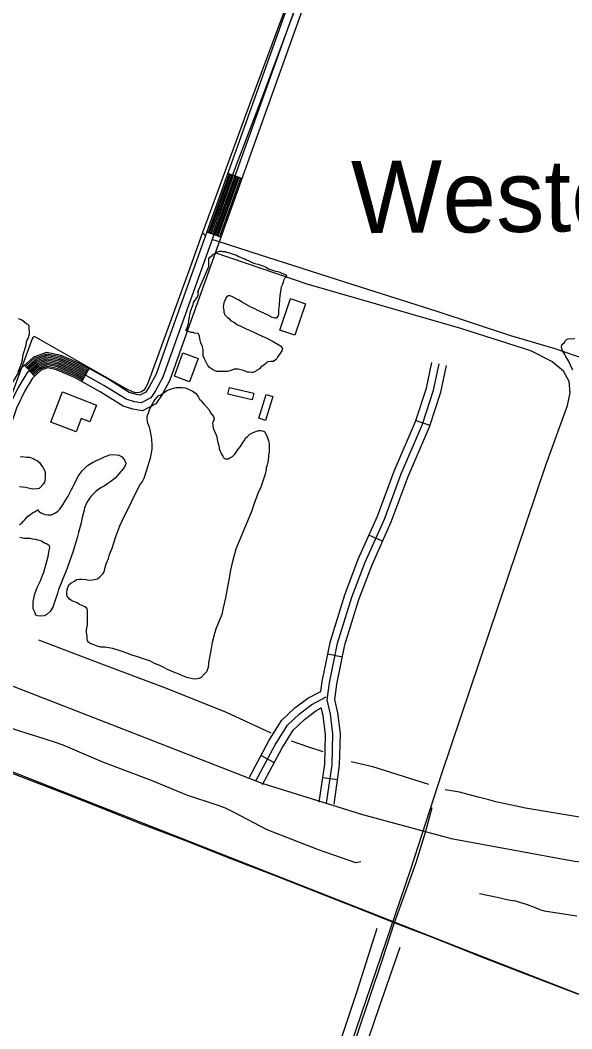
# Model space of a CAD drawing. Extents: x 3281947 to 3319794, y 715894 to 741249.
# Drawn here: x 3298836 to 3299944, y 722569 to 724593 of the extents above; entities that cross this region are included whole.
import ezdxf

# ---------------------------------------------------------------- set-up
doc = ezdxf.new("R2010")
doc.units = 0
for name, color, linetype in [('V-BLDG-OTLN', 7, 'Continuous'), ('V-DTCH-CNTR', 7, 'Continuous'), ('V-RAIL-TRAK', 7, 'Continuous'), ('V-ROAD-CNTR', 7, 'Continuous'), ('V-SITE-VEGE', 7, 'Continuous'), ('V-TOPO-GNAM-IDEN', 7, 'Continuous'), ('V-TOPO-SHOR', 7, 'Continuous')]:
    doc.layers.add(name, color=color, linetype=linetype)

msp = doc.modelspace()

# ---------------------------------------------------------------- linework, layer by layer
at = {"layer": 'V-BLDG-OTLN'}
for points in [[(3299357.2, 723971.1), (3299378.6, 724034.4), (3299409, 724024.1), (3299387.6, 723960.8)], [(3299145.4, 723878.8), (3299162.5, 723925.6), (3299193.1, 723914.3), (3299176, 723867.6)], [(3298920.4, 723847), (3298988.8, 723820.5), (3298975.8, 723787.1), (3298958.2, 723794), (3298947.7, 723766.9), (3298897, 723786.5)], [(3299256.3, 723856.2), (3299304.9, 723844.7), (3299301.7, 723831.1), (3299253, 723842.6)], [(3299315.1, 723794.2), (3299330, 723841.9), (3299343.4, 723837.7), (3299328.4, 723790)]]:
    msp.add_lwpolyline(points, close=True, dxfattribs=at)
at = {"layer": 'V-DTCH-CNTR'}
msp.add_lwpolyline([(3299410.4, 724679), (3299395.7, 724638.7), (3299325.7, 724449.5), (3299265.4, 724291.8), (3299225.3, 724183.4)], dxfattribs=at)
at = {"layer": 'V-RAIL-TRAK'}
for points in [[(3299849.3, 722679.2), (3299761, 722713.5), (3299663.5, 722752.2), (3299603.9, 722774.9), (3299586.9, 722781.6), (3299533.3, 722802.9), (3299451.7, 722834.9), (3299353.4, 722873.6), (3299260.9, 722909.2), (3299166.2, 722946.6), (3299076, 722981.2), (3298988.6, 723015.5), (3298928, 723039.5), (3298835.5, 723075.1), (3298749.5, 723108.4), (3298683, 723135.1), (3298600.1, 723166.2), (3298587.1, 723171.6), (3298582.8, 723173.4), (3298567.7, 723179.4)], [(3299955.5, 722638.3), (3299849.3, 722679.2)]]:
    msp.add_lwpolyline(points, dxfattribs=at)
at = {"layer": 'V-ROAD-CNTR'}
for p, q in [((3299280.7, 724275.3), (3299252.4, 724285.4)), ((3299238.6, 724157.6), (3299210.3, 724167.7)), ((3298864.3, 723878.5), (3298844.4, 723900.9)), ((3298959.4, 723867.8), (3298974, 723894)), ((3299630.3, 723789.9), (3299658.7, 723780.5)), ((3299536.5, 723559.9), (3299563.9, 723547.7)), ((3299453.5, 723321.2), (3299482.9, 723315.2)), ((3299319.6, 723117.7), (3299346, 723103.4)), ((3299443.4, 723073.2), (3299473.1, 723068.9))]:
    msp.add_line(p, q, dxfattribs=at)
for points in [[(3287528.8, 727489.4), (3288159.7, 727246.7), (3289159.6, 726857.6), (3289743.7, 726626.7), (3290210.1, 726446.4), (3290854.7, 726194.3), (3291198.3, 726062.1), (3292329.9, 725616.5), (3292874.1, 725407.4), (3293983.9, 724974.1), (3294772.1, 724664.7), (3295711.6, 724298), (3296794.9, 723876.7), (3297613.5, 723554.1), (3297991.8, 723406.1), (3298815.4, 723086.6), (3299719.3, 722731.4), (3300678.1, 722358.1)], [(3299923.8, 726089.6), (3299901, 726032), (3299863.6, 725936.1), (3299761.7, 725663.6), (3299511.6, 724964.9), (3299148.2, 723949.6), (3299122.2, 723876.9), (3299107.7, 723849.6), (3299098, 723835), (3299078.6, 723825), (3299065.5, 723827.2), (3299048.5, 723832.4), (3299003.8, 723860.3), (3298951.5, 723889.4), (3298913.2, 723905.8), (3298889.6, 723910.7), (3298870.1, 723903.7), (3298848.8, 723884.7), (3298831.4, 723856.2), (3298814, 723820.3), (3298730.5, 723575.4), (3298677.2, 723417.2), (3298650.5, 723323)], [(3299937.8, 726084), (3299915, 726026.5), (3299877.6, 725930.8), (3299775.8, 725658.5), (3299525.7, 724959.8), (3299162.3, 723944.6), (3299136, 723870.8), (3299120.6, 723841.9), (3299108.3, 723823.5), (3299081.1, 723809.3), (3299062, 723812.6), (3299042.2, 723818.6), (3298996.1, 723847.4), (3298944.8, 723875.9), (3298908.7, 723891.5), (3298890.7, 723895.2), (3298877.9, 723890.6), (3298860.4, 723875), (3298844.6, 723849), (3298827.9, 723814.6), (3298744.7, 723570.6), (3298691.5, 723412.7), (3298665, 723318.9)], [(3299763.5, 725711.2), (3299747.6, 725668.8), (3299497.4, 724969.9), (3299134.1, 723954.7), (3299108.5, 723882.9), (3299094.8, 723857.3), (3299087.7, 723846.6), (3299076.2, 723840.6), (3299068.9, 723841.8), (3299054.7, 723846.1), (3299011.4, 723873.2), (3298958.1, 723902.8), (3298917.7, 723920.2), (3298888.5, 723926.2), (3298862.3, 723916.8), (3298837.1, 723894.4), (3298818.3, 723863.4), (3298800.1, 723826), (3298716.3, 723580.2), (3298662.9, 723421.6), (3298636.1, 723327)], [(3293604.8, 725293.3), (3294762.1, 724839.9), (3295753.8, 724453.1), (3296714, 724076.6), (3298094.6, 723538.7), (3299007, 723184.6), (3299321, 723061.9), (3299523.3, 722999.2), (3299701.5, 722950.5), (3299949, 722905.2), (3300134.1, 722886.4), (3300314.5, 722877.1), (3300486.9, 722878.9), (3300681.3, 722895.7), (3300871.4, 722922.7), (3301027.9, 722958.5), (3301177.9, 722998.7), (3301318.6, 723046.1), (3301415.1, 723084.5), (3301509.5, 723122.5), (3301655.6, 723193.6), (3302010.6, 723367.2), (3302498.5, 723608.3), (3302680.4, 723698.6)], [(3299255.3, 724284.4), (3299213.1, 724166.7)], [(3299258.1, 724283.4), (3299216, 724165.7)], [(3299260.9, 724282.4), (3299218.8, 724164.7)], [(3299263.7, 724281.4), (3299221.6, 724163.7)], [(3299266.6, 724280.4), (3299224.4, 724162.7)], [(3299269.4, 724279.3), (3299227.3, 724161.7)], [(3299272.2, 724278.3), (3299230.1, 724160.6)], [(3299275, 724277.3), (3299232.9, 724159.6)], [(3299277.9, 724276.3), (3299235.7, 724158.6)], [(3299081.9, 721282.4), (3299325.2, 722021.3), (3299521.4, 722598.8), (3299619.3, 722887), (3299682.7, 723081.2), (3299891.5, 723700.1), (3299934.8, 723819.8), (3299940.3, 723845.4), (3299938.5, 723867.8), (3299926.8, 723889.1), (3299903.5, 723908.1), (3299861.3, 723929.8), (3299720.6, 723974.7), (3299412.1, 724063.4), (3299227.2, 724126.2)], [(3298972.5, 723891.4), (3298956.8, 723900.1), (3298916.8, 723917.4), (3298888.8, 723923.1), (3298863.8, 723914.2), (3298846.4, 723898.6)], [(3298971.1, 723888.8), (3298955.5, 723897.4), (3298915.9, 723914.5), (3298889, 723920), (3298865.4, 723911.6), (3298848.3, 723896.4)], [(3298969.6, 723886.1), (3298954.1, 723894.7), (3298915, 723911.6), (3298889.2, 723916.9), (3298867, 723909), (3298850.3, 723894.1)], [(3298968.2, 723883.5), (3298952.8, 723892), (3298914.1, 723908.7), (3298889.4, 723913.8), (3298868.5, 723906.3), (3298852.3, 723891.9)], [(3298966.7, 723880.9), (3298951.5, 723889.4), (3298913.2, 723905.8), (3298889.6, 723910.7), (3298870.1, 723903.7), (3298854.3, 723889.7)], [(3298965.2, 723878.3), (3298950.2, 723886.7), (3298912.3, 723903), (3298889.9, 723907.6), (3298871.6, 723901.1), (3298856.3, 723887.4)], [(3299439.4, 723246.1), (3299442.2, 723265.8), (3299458.8, 723346.8), (3299487.5, 723440.1), (3299514.8, 723511.3), (3299553.3, 723597.5), (3299586.8, 723688.2), (3299629.5, 723787.5), (3299651.6, 723854.7), (3299662.6, 723906.5)], [(3298963.8, 723875.7), (3298948.8, 723884), (3298911.4, 723900.1), (3298890.1, 723904.5), (3298873.2, 723898.4), (3298858.3, 723885.2)], [(3298962.3, 723873), (3298947.5, 723881.3), (3298910.5, 723897.2), (3298890.3, 723901.4), (3298874.8, 723895.8), (3298860.3, 723883)], [(3298960.9, 723870.4), (3298946.2, 723878.6), (3298909.6, 723894.3), (3298890.5, 723898.3), (3298876.3, 723893.2), (3298862.3, 723880.7)], [(3299451.1, 723021.6), (3299462.3, 723098.8), (3299463.9, 723160.6), (3299458.9, 723200.4), (3299452.1, 723228.8), (3299457, 723263.2), (3299473.3, 723343.1), (3299501.7, 723435.2), (3299528.7, 723505.6), (3299567.2, 723591.8), (3299600.7, 723682.6), (3299643.5, 723782.2), (3299666.1, 723850.8), (3299677.3, 723903.4)], [(3299466, 723019.4), (3299477.3, 723097.6), (3299478.9, 723161.3), (3299473.6, 723203.1), (3299467.3, 723229.5), (3299471.8, 723260.7), (3299487.9, 723339.3), (3299515.9, 723430.3), (3299542.5, 723499.8), (3299581.1, 723586.2), (3299614.7, 723677.1), (3299657.5, 723776.9), (3299680.6, 723846.9), (3299692, 723900.3)], [(3299295.9, 723073.6), (3299335.2, 723146.6), (3299360.7, 723187.5), (3299387.2, 723212.8), (3299413.6, 723232.5), (3299439.4, 723246.1)], [(3299309.1, 723066.5), (3299348.1, 723139), (3299372.4, 723178), (3299396.9, 723201.3), (3299421.7, 723219.8), (3299450.3, 723234.9)], [(3299322.3, 723059.4), (3299361.1, 723131.5), (3299384.1, 723168.4), (3299406.6, 723189.8), (3299429.7, 723207.1), (3299440.5, 723212.8)], [(3299436.3, 723023.7), (3299447.4, 723100.1), (3299448.9, 723159.8), (3299444.1, 723197.7), (3299440.5, 723212.8)], [(3299662.3, 723012.2), (3299655.1, 722985), (3299649, 722962.8)], [(3299649, 722962.8), (3299630.4, 722902), (3299608, 722840.6), (3299594.3, 722801.8), (3299586.9, 722781.6), (3299562.7, 722707.1), (3299512.6, 722558.3), (3299465.2, 722418.7), (3299418.7, 722280.2), (3299369.4, 722136), (3299315.6, 721976.3), (3299260.9, 721807.8), (3299216.8, 721675.4), (3299209, 721651.9), (3299171.4, 721533.2), (3299169.4, 721526.9), (3299127.9, 721398.7), (3299087.3, 721278.5)]]:
    msp.add_lwpolyline(points, dxfattribs=at)
at = {"layer": 'V-SITE-VEGE'}
for points in [[(3299192.7, 724048.2), (3299214.2, 724099.1), (3299214.2, 724110.4), (3299214.8, 724114.2), (3299216.6, 724117.9), (3299218.5, 724119.2), (3299221, 724121.1), (3299222.8, 724123), (3299226.6, 724124.9), (3299229.1, 724126.8), (3299235.3, 724129.4), (3299239.7, 724129.4), (3299242.2, 724128.8), (3299247.8, 724128.8), (3299250.3, 724127.6), (3299254.1, 724127), (3299259.1, 724125.2), (3299263.5, 724123.9), (3299269.8, 724121.5), (3299273.6, 724119.6), (3299280.5, 724116.6), (3299284.3, 724114.7), (3299286.8, 724114.1), (3299290.5, 724112.3), (3299294.9, 724110.4), (3299301.9, 724106.7), (3299306.9, 724104.9), (3299313.2, 724103.7), (3299323.2, 724100), (3299329.5, 724097.5), (3299334.5, 724094.5), (3299342.1, 724091.4), (3299348.4, 724089.6), (3299352.7, 724089), (3299357.1, 724087.8), (3299364.1, 724084), (3299368.5, 724082.8), (3299370.4, 724079.7), (3299368.5, 724076.6), (3299366.6, 724074.7), (3299364.8, 724070.9), (3299363.6, 724066.5), (3299362.3, 724064.6), (3299361.7, 724061.5), (3299359.9, 724057.1)], [(3299359.9, 724057.1), (3299357.5, 724044.5), (3299356.3, 724034.5), (3299355.8, 724020.7), (3299354.6, 724012.6), (3299354.7, 724004.4), (3299354.1, 724000), (3299349.7, 723995), (3299347.2, 723995), (3299341.6, 723996.2), (3299332.2, 724001.7), (3299327.8, 724003.6), (3299317.7, 724008.5), (3299311.4, 724011), (3299307, 724014.1), (3299298.8, 724017.1), (3299281.8, 724027), (3299274.9, 724031.3), (3299270.5, 724033.2), (3299262.3, 724038.1), (3299257.3, 724040), (3299253.6, 724039.9), (3299251.1, 724039.3), (3299248.6, 724035.5), (3299244.9, 724026.1), (3299243.1, 724017.9), (3299244.4, 724010.4), (3299244.4, 724007.3), (3299247, 724001.7), (3299252, 723996.7), (3299255.2, 723994.2), (3299258.3, 723990.5), (3299265.9, 723986.2), (3299270.9, 723982.5), (3299279.1, 723979.4), (3299289.8, 723973.8), (3299296.1, 723971.4), (3299304.9, 723967.1), (3299311.8, 723963.4), (3299321.9, 723959.1), (3299329.4, 723955.4), (3299343.9, 723948.6), (3299358.3, 723939.9), (3299362.8, 723934.3), (3299360.9, 723929.3), (3299352.3, 723916.7), (3299350.4, 723913), (3299348.5, 723911.7), (3299344.2, 723907.9), (3299339.2, 723907.9), (3299332.9, 723907.2), (3299331.1, 723905.9), (3299329.2, 723904), (3299325.4, 723901.5), (3299319.2, 723897), (3299316.1, 723893.3), (3299310.5, 723890.1), (3299308, 723888.2), (3299303, 723886.3), (3299299.9, 723886.2), (3299294.9, 723886.8), (3299292.4, 723886.8), (3299288.6, 723888), (3299284.2, 723889.9), (3299273.5, 723892.9), (3299265.4, 723892.8), (3299257.3, 723889.7), (3299252.3, 723888.4), (3299230.4, 723888.2), (3299226, 723890), (3299222.2, 723891.9), (3299215.9, 723896.2), (3299212.1, 723901.8), (3299207.6, 723909.3), (3299205.1, 723914.9), (3299203.2, 723919.9), (3299203.1, 723932.4), (3299201.1, 723940.6), (3299198.6, 723944.9), (3299196.6, 723954.3), (3299196, 723959.9), (3299194, 723963.7), (3299191.5, 723964.3), (3299185.3, 723964.9), (3299182.8, 723966.1), (3299179, 723966.1), (3299175.2, 723967.9), (3299172.7, 723968.5), (3299168.3, 723970.4), (3299170.2, 723973.5), (3299173.8, 723984.2), (3299175, 723994.2), (3299178, 724008.6), (3299180.5, 724016.2), (3299182.9, 724022.5), (3299183.5, 724026.8), (3299186.6, 724030.6), (3299190.9, 724036.9), (3299193.4, 724041.3), (3299194, 724045.7), (3299192.7, 724048.2)], [(3298831.8, 723994.6), (3298838.7, 723991.5), (3298841.8, 723989.6), (3298844.4, 723987.8), (3298848.8, 723984.1), (3298851.3, 723982.8), (3298853.2, 723979.1), (3298853.2, 723974.7), (3298853.9, 723967.2), (3298853.3, 723962.8), (3298851.5, 723955.9), (3298849.7, 723952.1), (3298847.8, 723947.1), (3298846.6, 723940.8), (3298843.6, 723929.5), (3298841.1, 723921.4), (3298838.7, 723908.2), (3298836.3, 723899.4), (3298830.8, 723886.8)], [(3299945.6, 723890.8), (3299941.1, 723900.8), (3299936.7, 723909.6), (3299931.6, 723918.3), (3299929.7, 723922), (3299925.2, 723930.1), (3299923.3, 723934.5), (3299922.7, 723937.6), (3299923.3, 723940.8), (3299925.1, 723943.3), (3299928.9, 723946.4), (3299930.1, 723949.6), (3299933.2, 723952.1), (3299936.3, 723954), (3299949.5, 723954.1)], [(3299041.1, 723589.8), (3299077.5, 723663.3), (3299079.3, 723664.6), (3299081.2, 723667.1), (3299084.3, 723674.1), (3299089.8, 723691), (3299097.1, 723714.9), (3299098.9, 723719.9), (3299100.7, 723733.1), (3299100.7, 723740.6), (3299099.9, 723752.5), (3299098.6, 723760.6), (3299096.6, 723771.2), (3299095.4, 723776.2), (3299092.2, 723784.3), (3299091.5, 723787.5), (3299090.8, 723793.1), (3299090.8, 723797.5), (3299093.8, 723807.5), (3299096.3, 723813.2), (3299101.2, 723823.3), (3299104.3, 723827.7), (3299106.2, 723831.4), (3299110.5, 723836.5), (3299113, 723839), (3299116.8, 723840.9), (3299123, 723844.7), (3299129.8, 723849.2), (3299133.6, 723851.1), (3299139.8, 723853.6), (3299149.2, 723856.2), (3299161.1, 723856.3), (3299167.4, 723855.1), (3299176.2, 723851.4), (3299181.2, 723849.6), (3299187.5, 723844.6), (3299191.3, 723840.9), (3299193.8, 723836.5), (3299195.7, 723832.8), (3299199.5, 723829.1), (3299200.8, 723826.6), (3299205.2, 723821.6), (3299209.6, 723817.2), (3299215.3, 723811), (3299217.9, 723805.4), (3299223.6, 723797.9), (3299225.5, 723793.6), (3299224.3, 723790.4), (3299222.4, 723787.3), (3299221.8, 723784.1), (3299222.5, 723781), (3299222.5, 723777.9), (3299224.4, 723771), (3299228.9, 723762.3), (3299230.8, 723757.3), (3299231.5, 723751.7), (3299232.8, 723745.4), (3299234.7, 723740.4), (3299235.4, 723732.9), (3299239.8, 723722.3), (3299242.4, 723717.9), (3299243.7, 723715.4), (3299246.2, 723713.6), (3299248.7, 723713), (3299253.1, 723713), (3299256.8, 723714.9), (3299262.4, 723717.5), (3299266.8, 723721.9), (3299273.6, 723732), (3299277.9, 723737.6), (3299282.9, 723745.8), (3299286, 723749.6), (3299288.4, 723754), (3299292.2, 723757.8), (3299297.1, 723762.2), (3299303.4, 723765.4), (3299314, 723769.9), (3299318.4, 723769.9), (3299324.7, 723768.1), (3299327.2, 723766.8), (3299331.6, 723756.8), (3299334.2, 723748.7), (3299335.5, 723743.7), (3299335.6, 723726.2), (3299334.4, 723720.5), (3299334.5, 723716.2), (3299333.3, 723706.1)], [(3298835.3, 723717.1), (3298839.7, 723717.2), (3298848.4, 723716), (3298854.1, 723716), (3298861.6, 723713.6), (3298864.8, 723711.7), (3298870.4, 723708.6), (3298874.2, 723705.5), (3298878.6, 723699.3), (3298881.2, 723696.2), (3298885, 723688.7), (3298885.7, 723684.3), (3298885.7, 723673.1), (3298884.5, 723666.2), (3298881.5, 723661.8), (3298876.5, 723656.1), (3298874, 723653.6), (3298869.6, 723652.3), (3298860.2, 723652.2), (3298846.4, 723655.2), (3298834.5, 723656.4)], [(3298885.7, 723601), (3298891.3, 723600.5), (3298898.2, 723600.5), (3298902.6, 723602.4), (3298906.3, 723604.3), (3298911.3, 723607.5), (3298915, 723611.9), (3298921.2, 723620.7), (3298926.2, 723628.3), (3298931.8, 723637.7), (3298938.5, 723651.6), (3298947.8, 723669.2), (3298950.9, 723675.5), (3298954, 723680.5), (3298960.1, 723688.7), (3298964.5, 723693.7), (3298970.7, 723699.4), (3298980.7, 723705.8), (3298988.8, 723709.6), (3298999.4, 723714.1), (3299005, 723716.6), (3299015.6, 723721.1), (3299023.1, 723721.8), (3299033.8, 723720), (3299040.1, 723716.9), (3299045.2, 723710.1), (3299047.7, 723704.4), (3299047.1, 723700.1), (3299044.6, 723695.7), (3299039.1, 723688.7), (3299037.2, 723686.8), (3299031, 723679.3), (3299026.7, 723674.2), (3299017.9, 723667.3), (3299011.7, 723663.4), (3299004.2, 723657.7), (3298998.6, 723655.2), (3298991.8, 723650.8), (3298987.4, 723647.6), (3298981.8, 723641.3), (3298977.5, 723636.9), (3298973.1, 723630.6), (3298969.4, 723624.9), (3298964.5, 723614.2), (3298963.9, 723609.8), (3298960.3, 723594.8), (3298957.9, 723584.1), (3298952.4, 723565.3), (3298950, 723554), (3298944.5, 723537), (3298942, 723527.6), (3298934.1, 723505), (3298929.8, 723493.7), (3298926.7, 723484.9), (3298921.2, 723472.3), (3298918.1, 723463.5), (3298912.6, 723450.9), (3298910.8, 723442.8), (3298905.9, 723429), (3298903.4, 723420.8), (3298901.6, 723416.4), (3298896, 723406.3), (3298889.8, 723401.3), (3298883.6, 723397.5), (3298876.1, 723396.8), (3298870.4, 723397.4), (3298867.3, 723399.2), (3298865.4, 723403.6), (3298861.6, 723411.7), (3298861.4, 723426.7), (3298865.1, 723441.8), (3298870, 723454.4), (3298875.5, 723466.3), (3298882.9, 723485.2), (3298888.4, 723504.6), (3298892, 723516.5), (3298893.2, 723525.3), (3298895, 723534.7), (3298894.3, 723538.5), (3298888.7, 723542.2), (3298884.3, 723543.4), (3298879.2, 723547.1)], [(3299333.3, 723706.1), (3299331.5, 723701.1), (3299329.6, 723694.8), (3299329.7, 723691.1), (3299327.9, 723682.3), (3299318.7, 723655.9), (3299313.1, 723643.3), (3299305.2, 723621.4), (3299300.3, 723606.9), (3299292.3, 723587.4), (3299278.8, 723555.4), (3299273.2, 723542.8), (3299268.9, 723531.5), (3299264.1, 723513.9), (3299261, 723501.4), (3299258, 723489.4), (3299254.4, 723470), (3299252, 723456.2), (3299247.8, 723433.6), (3299243.6, 723413.5), (3299240.6, 723400.4), (3299229.5, 723372.7), (3299225.8, 723362), (3299221, 723344.5), (3299219.2, 723331.9), (3299213.8, 723303.1), (3299213.2, 723294.3), (3299209.6, 723285.5), (3299205.2, 723280.5), (3299199, 723274.1), (3299194.6, 723271.6), (3299187.8, 723270.3), (3299181.5, 723271.5), (3299170.2, 723273.9), (3299163.9, 723276.4), (3299151.3, 723281.9), (3299146.9, 723283.1), (3299138.1, 723287.4), (3299132.5, 723289.3), (3299123, 723294.8), (3299116.1, 723297.9), (3299105.5, 723302.2), (3299096, 723307.1), (3299080.9, 723312), (3299072.1, 723315.7), (3299059.6, 723318.7), (3299052.1, 723321.8), (3299040.1, 723326.1), (3299032.6, 723328.5), (3299021.9, 723332.2), (3299005.6, 723334.6), (3298997.5, 723335.1), (3298989.9, 723337), (3298985.5, 723338.8), (3298976.1, 723342.5), (3298973, 723345), (3298971.1, 723347.4), (3298970.4, 723352.5), (3298970.3, 723357.5), (3298969, 723364.3), (3298969, 723369.4), (3298970.8, 723379.4), (3298970.6, 723408.8), (3298969.9, 723412), (3298968.6, 723413.8), (3298965.5, 723415.7), (3298961.7, 723417.5), (3298954.8, 723420.6), (3298949.8, 723423.7), (3298942.9, 723426.8), (3298938.5, 723428.6), (3298934.7, 723431.1), (3298933.4, 723433), (3298931.5, 723434.8), (3298929.6, 723439.2), (3298929.6, 723443.6), (3298930.1, 723450.5), (3298933.2, 723459.9), (3298937.6, 723463), (3298944.4, 723467.5), (3298948.8, 723470.7), (3298955, 723471.3), (3298959.4, 723471.4), (3298967.5, 723470.8), (3298971.9, 723469.6), (3298980.7, 723469.7), (3298987.6, 723471), (3298990.7, 723472.2), (3298996.3, 723476.7), (3299002.5, 723482.4), (3299004.4, 723486.1), (3299006.2, 723494.9), (3299008.6, 723501.8), (3299012.9, 723513.1), (3299014.7, 723520.7), (3299020.3, 723533.2), (3299023.3, 723542), (3299027.6, 723557.1), (3299031.9, 723567.8), (3299035.6, 723578.5), (3299041.1, 723589.8)], [(3298834.5, 723581.2), (3298838.2, 723583.1), (3298841.3, 723586.9), (3298844.5, 723589.4), (3298847.6, 723593.8), (3298850.7, 723597.6), (3298856.3, 723600.8), (3298860, 723604.6), (3298864.4, 723606.5), (3298871.2, 723610.3), (3298872.5, 723608.5), (3298874.4, 723606.6), (3298876.9, 723604.7), (3298885.7, 723601)], [(3298879.2, 723547.1), (3298877.4, 723548.4), (3298871.1, 723549.6), (3298866.7, 723550.8), (3298860.4, 723551.4), (3298855.4, 723552.6), (3298842.9, 723553.1), (3298834.7, 723554.9)]]:
    msp.add_lwpolyline(points, dxfattribs=at)
at = {"layer": 'V-TOPO-SHOR'}
msp.add_line((3299206.9, 724161.4), (3299202.1, 724166.8), dxfattribs=at)
for points in [[(3299444.4, 724819.2), (3299374.9, 724637), (3299296.4, 724424), (3299229.2, 724241.3), (3299202.1, 724166.8), (3299176.2, 724095.7), (3299099, 723882.6), (3299091.3, 723863), (3299088.1, 723856.9), (3299085.7, 723853.6), (3299083.9, 723850.8), (3299079.3, 723847.5), (3299074.6, 723846), (3299067.6, 723845), (3299061.5, 723847.3), (3299049.8, 723852.8), (3298963, 723902.5), (3298864.5, 723958.2), (3298861.7, 723957.3), (3298859.4, 723954), (3298804.2, 723802.3), (3298722.7, 723592.9), (3298663.2, 723449.1), (3298656.8, 723437.4)], [(3301429.5, 723440.5), (3301235.4, 723501.2), (3301073.4, 723557.3), (3300934.8, 723602.1), (3300779.8, 723648), (3300665.2, 723688.1), (3300580.8, 723717.6), (3300466.9, 723751.6), (3300285.8, 723811.7), (3300154.1, 723854.4), (3300044.3, 723890.5), (3299970.2, 723913.1), (3299910.5, 723933.9), (3299821.3, 723959.8), (3299673.1, 724008.6), (3299506.4, 724061.3), (3299316.4, 724122), (3299231.3, 724149.4), (3299220.7, 724153.3)], [(3299339.6, 723162), (3299249.7, 723203.6), (3299131.7, 723251.2), (3298999.6, 723301), (3298872.8, 723349.1)], [(3299519.8, 722903.7), (3299509.5, 722902.2), (3299434.6, 722928.2), (3299332, 722968.4), (3299265.4, 723002.9), (3299248.1, 723011.6), (3299231.2, 723017.6), (3299170.4, 723037.6), (3299099.6, 723067.4), (3299001.3, 723104), (3298921.7, 723137.9), (3298904.3, 723144.3), (3298887.5, 723149.7), (3298869.2, 723155.2), (3298853.8, 723160.2), (3298832.7, 723167), (3298786.8, 723181.6), (3298703, 723214.5), (3298635.3, 723243.8)], [(3299443.9, 723124.5), (3299415.1, 723134), (3299380.7, 723145.9)], [(3299656.5, 723059.2), (3299543.8, 723094.9), (3299500.2, 723104.5)], [(3299963, 722992.7), (3299850.8, 723011.4), (3299790.9, 723024.5), (3299776.9, 723028.6), (3299755.4, 723034), (3299717.9, 723044), (3299689.5, 723048.5)], [(3299758.1, 722840.6), (3299793.6, 722833), (3299816.5, 722828), (3299830.5, 722825.8), (3299840.8, 722822.6), (3299847.9, 722820.3), (3299854, 722818.1), (3299862.4, 722814.9), (3299871.3, 722811.7), (3299879.7, 722808.5), (3299888.1, 722805.3), (3299954, 722795.5)], [(3299552.1, 722770.4), (3299511.5, 722643.6), (3299456.8, 722479.3), (3299423.5, 722388.4), (3299380.8, 722245.2), (3299339.8, 722119.7), (3299297.3, 721994.3), (3299252.2, 721860.4), (3299202.1, 721711.5), (3299155.7, 721559.9), (3299151.5, 721552.8)], [(3299598.1, 722732.1), (3299555.2, 722608.9), (3299495.5, 722434.3), (3299458.1, 722317.3)]]:
    msp.add_lwpolyline(points, dxfattribs=at)

# ---------------------------------------------------------------- texts
at = {"layer": 'V-TOPO-GNAM-IDEN'}
msp.add_text('Westover', height=145, rotation=0.4943, dxfattribs=at).set_placement((3299501.2, 724165.4))

doc.saveas('drawing.dxf')
